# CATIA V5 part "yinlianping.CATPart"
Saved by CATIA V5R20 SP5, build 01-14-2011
Part number: yingliaoping
Material "Sunset"
Material "Summer sky"
Bounding box of the stored display mesh (mm): x -25 to 26, y -25 to 25, z 0 to 110
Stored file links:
  E:\180222134\成品\yingliaoping.CATPart
  C:\Program Files\Dassault Systemes\B20\intel_a\startup\materials\Catalog.CATMaterial
  C:\Program Files\Dassault Systemes\B20\intel_a\startup\materials\fence_3.jpg
  C:\Program Files\Dassault Systemes\B20\intel_a\startup\materials\canvas.jpg
  C:\Program Files\Dassault Systemes\B20\intel_a\startup\materials\brown_fiber.jpg
  C:\Program Files\Dassault Systemes\B20\intel_a\startup\materials\marble_paving.jpg
  C:\Program Files\Dassault Systemes\B20\intel_a\startup\materials\old_tile.jpg
  C:\Program Files\Dassault Systemes\B20\intel_a\startup\materials\wall_of_bricks.jpg
  C:\Program Files\Dassault Systemes\B20\intel_a\startup\materials\roughcast.jpg
  C:\Program Files\Dassault Systemes\B20\intel_a\startup\materials\grid.png
  C:\Program Files\Dassault Systemes\B20\intel_a\startup\materials\blue_env_512x512.jpg
  C:\Program Files\Dassault Systemes\B20\intel_a\startup\materials\DS_star.jpg
  C:\Program Files\Dassault Systemes\B20\intel_a\startup\materials\chessboard.jpg
  C:\Program Files\Dassault Systemes\B20\intel_a\startup\materials\sunset.jpg
  C:\Program Files\Dassault Systemes\B20\intel_a\startup\materials\summer_sky.jpg
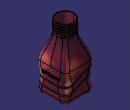
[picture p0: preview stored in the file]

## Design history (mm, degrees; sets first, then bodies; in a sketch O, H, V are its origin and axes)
Set1
  Sketch1 on xy-plane, origin (0, 0, 0), H (1, 0, 0), V (0, 1, 0)
    line L1 (25, 25) -> (25, -25)
    line L2 (25, -25) -> (-25, -25)
    line L3 (-25, -25) -> (-25, 25)
    line L4 (-25, 25) -> (25, 25)
    length L4 = 50
    length L1 = 50
    vertical: L1 V, L3 V
    horizontal: L2 H, L4 H
    equidistance: L1 L3 O, L2 L4 O
  Sketch2 on face of Pad1 from Sketch1.L2, origin (0, -25, 0), H (1, 0, 0), V (0, 0, 1)
    spline S1 through (-40.13, 17.5064) (-4.5865, 26.557) (17.4166, 15.9725) (37.4194, 24.256)
  Extrude1: Element1 Sketch2, Lim1 60, Lim2 60
  MultiSel1: CommonCtxFeats ({extract ExtractElem face of Pad1 from Sketch1.L2}; {extract ExtractElem face of Fillet1}; {extract ExtractElem face of Pad1 from Sketch1.L1}; {extract ExtractElem face of Fillet1}; {extract ExtractElem face of Pad1 from Sketch1.L4}; {extract ExtractElem face of Fillet1}; {extract ExtractElem face of Pad1 from Sketch1.L3}; {extract ExtractElem face of Fillet1}; {join Elements ({intersect ToIntersect1 {extract ExtractElem face of Pad1 from Sketch1.L2}, ToIntersect2 Extrude1}; {intersect ToIntersect1 {extract ExtractElem face of Fillet1}, ToIntersect2 Extrude1}; {intersect ToIntersect1 {extract ExtractElem face of Pad1 from Sketch1.L1}, ToIntersect2 Extrude1}; {intersect ToIntersect1 {extract ExtractElem face of Pad1 from Sketch1.L4}, ToIntersect2 Extrude1}; {intersect ToIntersect1 {extract ExtractElem face of Fillet1}, ToIntersect2 Extrude1}; {intersect ToIntersect1 {extract ExtractElem face of Fillet1}, ToIntersect2 Extrude1}; {intersect ToIntersect1 {extract ExtractElem face of Pad1 from Sketch1.L3}, ToIntersect2 Extrude1}; {intersect ToIntersect1 {extract ExtractElem face of Fillet1}, ToIntersect2 Extrude1})})
  Sketch3 on face of Pad1 from Sketch1.L2, origin (0, -25, 0), H (1, 0, 0), V (0, 0, 1)
    spline S1 through (-31.3579, 34.1236) (-14.7105, 40.4955) (13.6792, 27.8998) (28.8403, 27.8998)
  Extrude2: Element1 Sketch3, Lim1 60, Lim2 60
  MultiSel2: CommonCtxFeats ({extract ExtractElem face of Fillet1}; {extract ExtractElem face of Pad1 from Sketch1.L1}; {extract ExtractElem face of Fillet1}; {extract ExtractElem face of Pad1 from Sketch1.L4}; {extract ExtractElem face of Fillet1}; {extract ExtractElem face of Pad1 from Sketch1.L3}; {extract ExtractElem face of Fillet1}; {extract ExtractElem face of Pad1 from Sketch1.L2}; {join Elements ({intersect ToIntersect1 {extract ExtractElem face of Fillet1}, ToIntersect2 Extrude2}; {intersect ToIntersect1 {extract ExtractElem face of Pad1 from Sketch1.L1}, ToIntersect2 Extrude2}; {intersect ToIntersect1 {extract ExtractElem face of Fillet1}, ToIntersect2 Extrude2}; {intersect ToIntersect1 {extract ExtractElem face of Pad1 from Sketch1.L4}, ToIntersect2 Extrude2}; {intersect ToIntersect1 {extract ExtractElem face of Fillet1}, ToIntersect2 Extrude2}; {intersect ToIntersect1 {extract ExtractElem face of Pad1 from Sketch1.L3}, ToIntersect2 Extrude2}; {intersect ToIntersect1 {extract ExtractElem face of Fillet1}, ToIntersect2 Extrude2}; {intersect ToIntersect1 {extract ExtractElem face of Pad1 from Sketch1.L2}, ToIntersect2 Extrude2})})
  Plane1: type Normal, Curve {intersect ToIntersect1 {extract ExtractElem face of Pad1 from Sketch1.L4}, ToIntersect2 Extrude2}, RefPoint vertex of MultiSel2
  Sketch4 on Plane1, origin (-17.4023, 0, 0.6186), H (0, 1, 0), V (0.0355, 0, 0.9994)
    circle A1 centre (25.3111, 40.1619) radius 1
    radius A1 = 1
  Plane2: type Normal, Curve {intersect ToIntersect1 {join Elements ({intersect ToIntersect2 Extrude1}; {intersect ToIntersect2 Extrude1}; {intersect ToIntersect2 Extrude1}; {intersect ToIntersect2 Extrude1}; {intersect ToIntersect2 Extrude1}; {intersect ToIntersect2 Extrude1}; {intersect ToIntersect2 Extrude1}; {intersect ToIntersect2 Extrude1})}, ToIntersect2 Extrude1}, RefPoint vertex of MultiSel1
  Sketch5 on Plane2, origin (-17.7485, 0, 3.598), H (0, -1, 0), V (0.1987, 0, 0.9801)
    circle A1 centre (-24.9885, 25.9108) radius 1
    radius A1 = 1
Body1 (main body), material "Sunset"
  Pad1: profile Sketch1, direction (0, 0, 1), length 50
  Fillet1: on edge [face of Pad1 from Sketch1.L4 | face of Pad1 from Sketch1.L1]; edge [face of Pad1 from Sketch1.L3 | face of Pad1 from Sketch1.L4]; edge [face of Pad1 from Sketch1.L1 | face of Pad1 from Sketch1.L2]; edge [face of Pad1 from Sketch1.L2 | face of Pad1 from Sketch1.L3]
  Fillet2: radius 8, on edge [start face of Pad1 | face of Pad1 from Sketch1.L1]
  Plane3: type Offset, RefPlane end face of Pad1, Offset 40, reversed
  Sketch6 on Plane3, origin (0, 0, 90), H (1, 0, 0), V (0, -1, 0)
    circle A1 centre (0, 0) radius 15
    radius A1 = 15
  Pad2: profile Sketch6, direction (0, 0, 1), length 20
  Sketch7 on end face of Pad1, origin (0, 0, 50), H (1, 0, 0), V (0, 1, 0)
    point P1 (25, 0)
    distance P1 O = 25
    coincidence: P1 H
  Sketch8 on start face of Pad2, origin (0, 0, 90), H (1, 0, 0), V (0, -1, 0)
    point P1 (15, 0)
    distance P1 O = 15
    coincidence: P1 H
  Loft1: solid, Sections ({boundary Boundary {extract ExtractElem end face of Pad1}}; {boundary Boundary {extract ExtractElem start face of Pad2}}), StartFace end face of Pad1, EndFace start face of Pad2
  Slot1: profile Sketch4, centre curve {intersect ToIntersect1 {join}, ToIntersect2 Extrude2}
  Slot2: profile Sketch5, centre curve {intersect ToIntersect1 {join}, ToIntersect2 Extrude1}
  Shell1: ExtOffset 0, Face end face of Pad2, IntOffset 1
  Plane4: type Offset, RefPlane {extract ExtractElem start face of Pad2}, Offset 2
  Sketch9 on Plane4, origin (0, 0, 92), H (1, 0, 0), V (0, 1, 0)
    point P1 (15, 0)
    distance P1 O = 15
    coincidence: P1 H
  Helix1: Direction Z axis, RefPoint Sketch9, Pitch 3, Height 16, TaperAngle 0
  Line1: type PtDir, RefPoint Sketch9, Direction (1, 0, 0), Start 0, End 5
  Line2: type PtDir, RefPoint vertex of Helix1, Direction (0, 1, 0), Start 0, End 5
  Point1: type OnCurve, Support Helix1, Length 6.943
  Point2: type OnCurve, Support Helix1, RefPoint vertex of Helix1, Length -5.555
  Connect1: Curve1 Line2, Point1 vertex of Line2, Tension1 1, Curve2 Helix1, Point2 Point2, Tension2 1
  Connect2: Curve1 Line1, Point1 vertex of Line1, Tension1 1, Curve2 Connect1, Point2 Point1, Tension2 1
  Plane5: type Normal, Curve Connect2, RefPoint vertex of Connect2
  Sketch10 on Plane5, origin (10, 0, 0), H (0, 1, 0), V (0, 0, 1)
    circle A1 centre (0, 92.0244) radius 0.5
    point P1 (0, 92.0244)
    radius A1 = 0.5
    coincidence: P1 V
  Rib1: profile Sketch10, centre curve Connect2, thin wall 10
  Body2
    Sketch11 on Plane4, origin (0, 0, 92), H (1, 0, 0), V (0, 1, 0)
      circle A1 centre (0, 0) radius 14
      radius A1 = 14
    Pad3: profile Sketch11, direction (0, 0, -1), length 20, mirrored extent
  Remove1: tool Body2
Body3, material "Summer sky"
  Sketch12 on face of Pad1 from Sketch1.L1, origin (25, 0, 0), H (0, 1, 0), V (0, 0, 1)
    polyline C1
    polyline C2
    polyline C3
    polyline C4
    polyline C5
    polyline C6
    polyline C7
    polyline C8
    polyline C9
    polyline C10
    polyline C11
  Pocket1: profile Sketch12, direction (1, 0, 0), length 1
  Sketch13 on Plane4, origin (0, 0, 92), H (1, 0, 0), V (0, 1, 0)
    circle A1 centre (0, 0) radius 15
    radius A1 = 15
  Pad4: profile Sketch13, direction (0, 0, 1), length 20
